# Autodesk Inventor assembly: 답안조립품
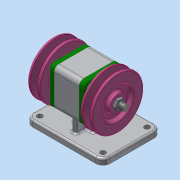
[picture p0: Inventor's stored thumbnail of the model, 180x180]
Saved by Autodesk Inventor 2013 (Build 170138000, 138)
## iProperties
Created: 2020-11
Part Number: 답안조립품
Document SubType Name: Assembly
Designer: Administrator
Author: Administrator
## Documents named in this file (10)
- C:\Users\Administrator\Desktop\701106V1017\답안조립품.iam
- C:\Users\Administrator\Desktop\701106V1017\본체.ipt
- C:\Users\Administrator\Desktop\701106V1017\베어링 6004.ipt
- C:\Users\Administrator\Desktop\701106V1017\볼트 M4.ipt
- C:\Users\Administrator\Desktop\701106V1017\오일 실 17 30 5.ipt
- C:\Users\Administrator\Desktop\701106V1017\커버.ipt
- C:\Users\Administrator\Desktop\701106V1017\축.ipt
- C:\Users\Administrator\Desktop\701106V1017\V-벨트풀리.ipt
- C:\Users\Administrator\Desktop\701106V1017\키 5 x 5 x 12.ipt
- C:\Users\Administrator\Desktop\701106V1017\너트 M10x1.ipt
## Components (2 placed, 1 different names)
1. V-벨트풀리:1 — 각도:4
2. V-벨트풀리:2 — 각도:3
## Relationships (2: Angle 2)
- 각도:3 [Angle]: V-벨트풀리:2
- 각도:4 [Angle]: V-벨트풀리:1
